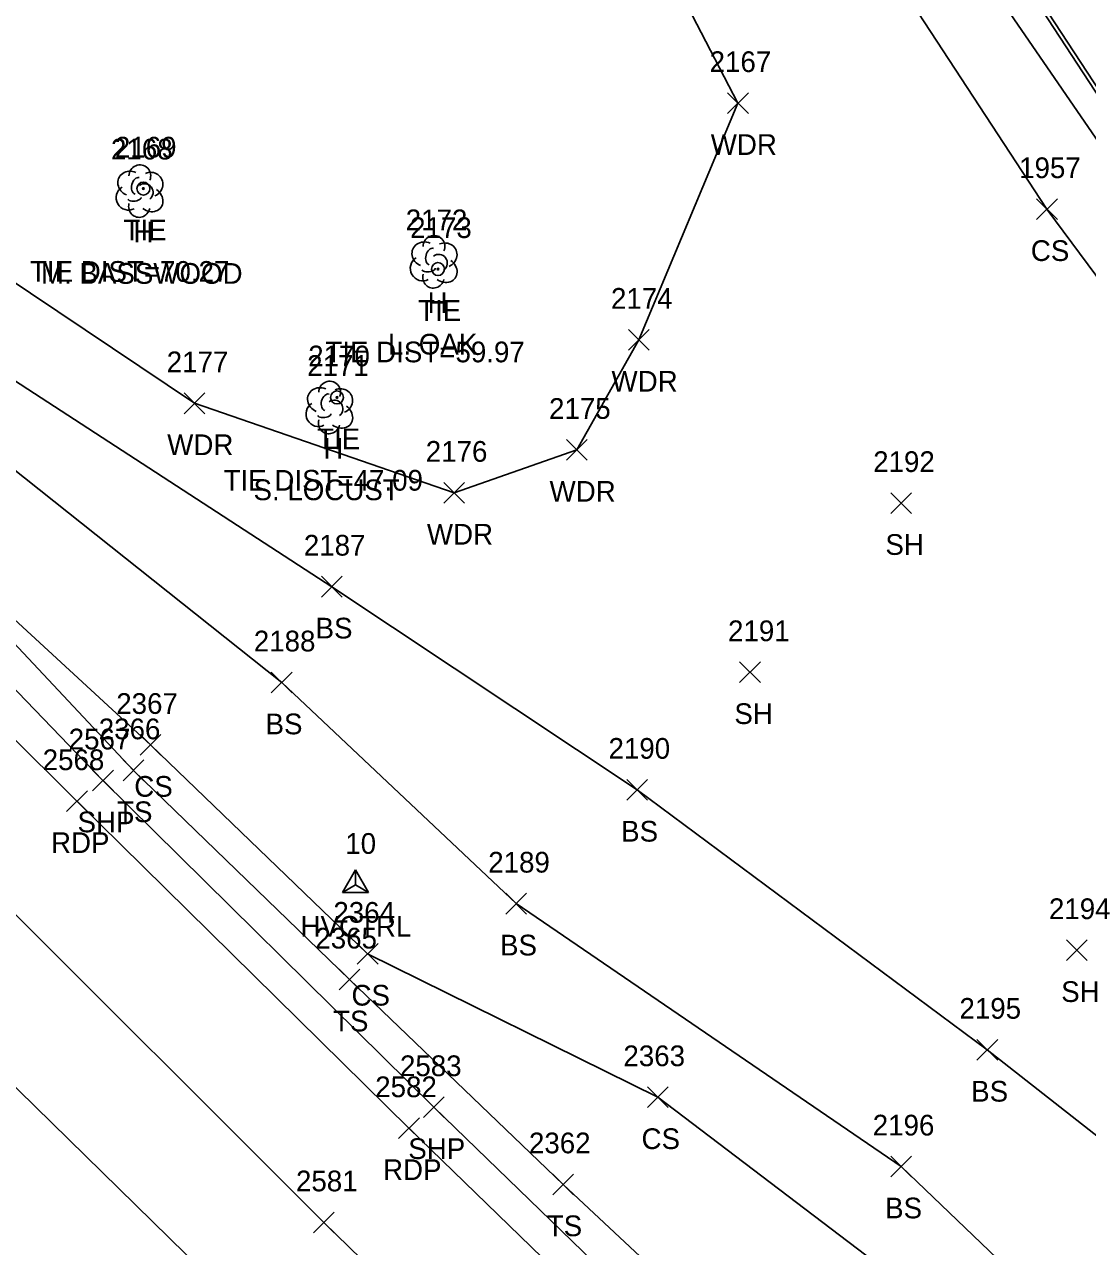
# Model space of a CAD drawing. Extents: x 1647574 to 1652703, y 212895 to 228670.
# Drawn here: x 1648054.3 to 1648157, y 227963.7 to 228081.7 of the extents above; entities that cross this region are included whole.
import ezdxf

# ---------------------------------------------------------------- set-up
doc = ezdxf.new("R2010")
doc.units = 0
for name, color, linetype in [('C_A', 7, 'Continuous'), ('C_C', 7, 'Continuous'), ('C_I', 7, 'Continuous'), ('CBP', 7, 'Continuous'), ('CPSM', 7, 'Continuous'), ('L_A', 7, 'Continuous'), ('L_C', 7, 'Continuous'), ('L_I', 7, 'Continuous'), ('L_TIC', 7, 'Continuous'), ('LAWA', 7, 'Continuous'), ('LELB', 7, 'Continuous'), ('LTD', 7, 'Continuous'), ('P_A', 7, 'Continuous'), ('P_I', 7, 'Continuous'), ('P_TIC', 7, 'Continuous'), ('PET', 7, 'Continuous'), ('PRC', 7, 'Continuous'), ('PSP', 7, 'Continuous'), ('RGR', 7, 'Continuous')]:
    doc.layers.add(name, color=color, linetype=linetype)

msp = doc.modelspace()

# ---------------------------------------------------------------- linework, layer by layer
at = {"layer": 'CBP'}
for centre, radius in [((1648065.82, 228065.87), 0.625), ((1648065.82, 228065.87), 0.0833), ((1648094.26, 228058.1), 0.625), ((1648094.26, 228058.1), 0.0833), ((1648084.51, 228045.71), 0.625), ((1648084.51, 228045.71), 0.0833)]:
    msp.add_circle(centre, radius, dxfattribs=at)
at = {"layer": 'CPSM'}
for p, q in [((1648085.05, 227997.93), (1648086.3, 228000.1)), ((1648087.55, 227997.93), (1648086.3, 228000.1)), ((1648086.3, 227998.65), (1648086.3, 228000.1)), ((1648085.05, 227997.93), (1648086.3, 227998.65)), ((1648086.3, 227998.65), (1648086.3, 227998.65)), ((1648086.3, 227998.65), (1648087.55, 227997.93)), ((1648085.05, 227997.93), (1648087.55, 227997.93))]:
    msp.add_line(p, q, dxfattribs=at)
at = {"layer": 'L_TIC'}
for points in [[(1648122.22, 228073.12), (1648124.22, 228075.12)], [(1648124.22, 228073.12), (1648122.22, 228075.12)], [(1648152.05, 228062.88), (1648154.05, 228064.88)], [(1648154.05, 228062.88), (1648152.05, 228064.88)], [(1648112.65, 228050.27), (1648114.65, 228052.27)], [(1648114.65, 228050.27), (1648112.65, 228052.27)], [(1648069.76, 228044.14), (1648071.76, 228046.14)], [(1648071.76, 228044.14), (1648069.76, 228046.14)], [(1648106.67, 228039.64), (1648108.67, 228041.64)], [(1648108.67, 228039.64), (1648106.67, 228041.64)], [(1648094.83, 228035.5), (1648096.83, 228037.5)], [(1648096.83, 228035.5), (1648094.83, 228037.5)], [(1648137.96, 228034.51), (1648139.96, 228036.51)], [(1648139.96, 228034.51), (1648137.96, 228036.51)], [(1648083, 228026.44), (1648085, 228028.44)], [(1648085, 228026.44), (1648083, 228028.44)], [(1648123.38, 228018.18), (1648125.38, 228020.18)], [(1648125.38, 228018.18), (1648123.38, 228020.18)], [(1648078.17, 228017.19), (1648080.17, 228019.19)], [(1648080.17, 228017.19), (1648078.17, 228019.19)], [(1648065.5, 228011.16), (1648067.5, 228013.16)], [(1648067.5, 228011.16), (1648065.5, 228013.16)], [(1648063.87, 228008.71), (1648065.87, 228010.71)], [(1648065.87, 228008.71), (1648063.87, 228010.71)], [(1648112.5, 228006.83), (1648114.5, 228008.83)], [(1648114.5, 228006.83), (1648112.5, 228008.83)], [(1648100.81, 227995.84), (1648102.81, 227997.84)], [(1648102.81, 227995.84), (1648100.81, 227997.84)], [(1648086.47, 227991), (1648088.47, 227993)], [(1648088.47, 227991), (1648086.47, 227993)], [(1648154.93, 227991.35), (1648156.93, 227993.35)], [(1648156.93, 227991.35), (1648154.93, 227993.35)], [(1648084.72, 227988.51), (1648086.72, 227990.51)], [(1648086.72, 227988.51), (1648084.72, 227990.51)], [(1648146.29, 227981.73), (1648148.29, 227983.73)], [(1648148.29, 227981.73), (1648146.29, 227983.73)], [(1648114.47, 227977.15), (1648116.47, 227979.15)], [(1648116.47, 227977.15), (1648114.47, 227979.15)], [(1648137.98, 227970.46), (1648139.98, 227972.46)], [(1648139.98, 227970.46), (1648137.98, 227972.46)], [(1648105.35, 227968.74), (1648107.35, 227970.74)], [(1648107.35, 227968.74), (1648105.35, 227970.74)]]:
    msp.add_lwpolyline(points, dxfattribs=at)
at = {"layer": 'LAWA'}
msp.add_lwpolyline([(1648003.3, 228303.1), (1648022.05, 228264.55), (1648045.55, 228226.26), (1648063.03, 228190.18), (1648079.22, 228154.91), (1648094.78, 228128.33), (1648111.3, 228097.1), (1648123.22, 228074.12), (1648113.65, 228051.27), (1648107.67, 228040.64), (1648095.83, 228036.5), (1648070.76, 228045.14), (1648046.97, 228061.07), (1648019.44, 228076.6), (1648008.75, 228083.44)], dxfattribs=at)
at = {"layer": 'LELB'}
for points in [[(1648351.84, 227812.3), (1648319.03, 227851.85), (1648287.09, 227892.13), (1648260.82, 227925.49), (1648232.83, 227963.62), (1648207.81, 227997.28), (1648182.57, 228032.91), (1648159.55, 228068.16), (1648135.13, 228103.7), (1648112.63, 228139.57), (1648088.44, 228176.61), (1648065.81, 228216.55), (1648048.77, 228244.34), (1648030.34, 228278.62), (1648010.32, 228316.28), (1647988.24, 228358.51), (1647969.05, 228396.12), (1647949.58, 228436.76), (1647932.55, 228474.27), (1647912.45, 228518.68), (1647893.94, 228561.09), (1647881.68, 228593.27), (1647863.51, 228642.93)], [(1648221.55, 227860.25), (1648189.85, 227891.44), (1648160.7, 227918.22), (1648135.07, 227942.85), (1648106.35, 227969.74), (1648085.72, 227989.51), (1648064.87, 228009.71), (1648037.27, 228039.1), (1648017.95, 228060.31), (1648000.53, 228079.89), (1647992.37, 228088.82), (1647945.75, 228138.02), (1647922.11, 228164.99), (1647896.22, 228195.21), (1647876.56, 228219.26), (1647857.99, 228244.57), (1647835.09, 228273.26), (1647814.45, 228301.43), (1647791.61, 228332.49), (1647765.76, 228369.8)], [(1648525.46, 227617.36), (1648497.47, 227646.51), (1648467.28, 227678.49), (1648435.31, 227710.73), (1648407.17, 227742.36), (1648379.63, 227772.76), (1648347.94, 227809.77), (1648315.69, 227849.46), (1648282.72, 227890.46), (1648255.42, 227922.98), (1648228.95, 227959.79), (1648203.39, 227994.31), (1648178.45, 228029.64), (1648153.05, 228063.88), (1648128.81, 228100.92), (1648107.87, 228136.93)], [(1648005.17, 228084.65), (1648023.65, 228068.5), (1648050.66, 228049.08), (1648084, 228027.44), (1648113.5, 228007.83), (1648147.29, 227982.73), (1648182.2, 227955.34), (1648213, 227923.38), (1648241.53, 227889), (1648267.07, 227861.14), (1648299.05, 227827.09), (1648330.77, 227794.94), (1648361.15, 227762.57), (1648392.5, 227731.8), (1648431.64, 227692.37), (1648464.56, 227657.5), (1648493.11, 227630.36), (1648521, 227603.29), (1648553.55, 227572.08), (1648564.74, 227563.33)], [(1648003.1, 228082.75), (1648021.4, 228065.95), (1648044.73, 228045.59), (1648079.17, 228018.19), (1648101.81, 227996.84), (1648138.98, 227971.46), (1648165.99, 227945.56), (1648168.81, 227943.47), (1648170.35, 227941.98), (1648172.46, 227939.54), (1648204.47, 227916.76), (1648236.47, 227884.75), (1648262.27, 227857.29), (1648293.8, 227821.06), (1648324.53, 227790.88), (1648359.53, 227760.77), (1648386.88, 227728.2), (1648427.75, 227689.04), (1648461.36, 227653.83), (1648490.92, 227628.14), (1648517.86, 227599.3), (1648549.31, 227568.74), (1648557.52, 227558.9)], [(1648258.63, 227840.47), (1648232.75, 227869.94), (1648204.84, 227901.15), (1648170.7, 227930.27), (1648148.94, 227952.73), (1648115.47, 227978.15), (1648087.47, 227992), (1648066.5, 228012.16), (1648037.27, 228039.1)]]:
    msp.add_lwpolyline(points, dxfattribs=at)
at = {"layer": 'LTD'}
for p, q in [((1648065.43, 228065.68), (1648065.43, 228065.68)), ((1648065.43, 228065.68), (1648065.43, 228065.68)), ((1648093.83, 228058.85), (1648093.83, 228058.85)), ((1648093.83, 228058.85), (1648093.83, 228058.85)), ((1648083.75, 228044.79), (1648083.75, 228044.79)), ((1648083.75, 228044.79), (1648083.75, 228044.79))]:
    msp.add_line(p, q, dxfattribs=at)
for centre in [(1648065.48, 228067.11), (1648093.87, 228060.29), (1648083.8, 228046.22)]:
    msp.add_arc(centre, 1.05, 335.5272, 180.9563, dxfattribs=at)
for centre, major_axis, ratio, start_param, end_param in [((1648064.64, 228066.35), (1.21, -0.51), 0.895232, 1.570796, 4.712389), ((1648065.22, 228066.14), (-0.208, -0.792), 0.645439, 3.141593, 6.283185), ((1648066.47, 228066.26), (-1.14, -0.48), 0.949671, 1.570796, 4.712389), ((1648064.35, 228064.97), (0.58, -1.04), 0.959034, 3.141593, 6.283185), ((1648065.93, 228065.51), (-0.5, 0.667), 0.989748, 3.141593, 6.283185), ((1648066.43, 228064.85), (-1.09, 0.79), 0.841452, 1.570796, 4.712389), ((1648064.98, 228064.93), (-0.625, -0.083), 0.423636, 0, 3.141593), ((1648065.43, 228064.18), (0.26, 1.06), 0.942809, 1.570796, 4.712389), ((1648093.04, 228059.52), (1.21, -0.51), 0.895232, 1.570796, 4.712389), ((1648093.62, 228059.31), (-0.208, -0.792), 0.645439, 3.141593, 6.283185), ((1648094.87, 228059.44), (-1.14, -0.48), 0.949671, 1.570796, 4.712389), ((1648092.74, 228058.14), (0.58, -1.04), 0.959034, 3.141593, 6.283185), ((1648094.33, 228058.69), (-0.5, 0.667), 0.989748, 3.141593, 6.283185), ((1648094.83, 228058.02), (-1.09, 0.79), 0.841452, 1.570796, 4.712389), ((1648093.83, 228057.35), (0.26, 1.06), 0.942809, 1.570796, 4.712389), ((1648093.37, 228058.1), (-0.625, -0.083), 0.423636, 0, 3.141593), ((1648082.96, 228045.45), (1.21, -0.51), 0.895232, 1.570796, 4.712389), ((1648083.54, 228045.24), (-0.208, -0.792), 0.645439, 3.141593, 6.283185), ((1648084.79, 228045.37), (-1.14, -0.48), 0.949671, 1.570796, 4.712389), ((1648082.67, 228044.08), (0.58, -1.04), 0.959034, 3.141593, 6.283185), ((1648084.25, 228044.62), (-0.5, 0.667), 0.989748, 3.141593, 6.283185), ((1648084.75, 228043.95), (-1.09, 0.79), 0.841452, 1.570796, 4.712389), ((1648083.75, 228043.29), (0.26, 1.06), 0.942809, 1.570796, 4.712389), ((1648083.29, 228044.04), (-0.625, -0.083), 0.423636, 0, 3.141593)]:
    msp.add_ellipse(centre, major_axis=major_axis, ratio=ratio, start_param=start_param, end_param=end_param, dxfattribs=at)
at = {"layer": 'P_TIC'}
for points in [[(1648060.92, 228007.73), (1648062.92, 228009.73)], [(1648062.92, 228007.73), (1648060.92, 228009.73)], [(1648058.41, 228005.73), (1648060.41, 228007.73)], [(1648060.41, 228005.73), (1648058.41, 228007.73)], [(1648092.85, 227976.19), (1648094.85, 227978.19)], [(1648094.85, 227976.19), (1648092.85, 227978.19)], [(1648090.46, 227974.16), (1648092.46, 227976.16)], [(1648092.46, 227974.16), (1648090.46, 227976.16)], [(1648082.25, 227965.07), (1648084.25, 227967.07)], [(1648084.25, 227965.07), (1648082.25, 227967.07)]]:
    msp.add_lwpolyline(points, dxfattribs=at)
at = {"layer": 'PET'}
for points in [[(1647624.94, 228569.41), (1647649.21, 228527.47), (1647673.22, 228488.91), (1647696.93, 228451.78), (1647721.59, 228414.82), (1647750.94, 228372.42), (1647776.24, 228337.3), (1647805.83, 228297.37), (1647832.4, 228262.54), (1647856.48, 228231.21), (1647884.54, 228196.61), (1647905.36, 228171.61), (1647936.05, 228137.05), (1647968.13, 228101.78), (1648000.62, 228066.78), (1648032.05, 228033.93), (1648059.41, 228006.73), (1648091.46, 227975.16), (1648125.8, 227941.82), (1648150.48, 227917.83), (1648178.42, 227890.8), (1648211.42, 227859.5)], [(1647604.45, 228556.69), (1647628.71, 228515.19), (1647652.82, 228475.82), (1647676.57, 228438.99), (1647701.85, 228401.16), (1647731.05, 228358.87), (1647757.42, 228322.24), (1647786.09, 228283.45), (1647812.17, 228249.47), (1647837.79, 228216.43), (1647865.75, 228182.07), (1647886.59, 228156.84), (1647918.79, 228120.52), (1647950.65, 228085.51), (1647982.59, 228051.21), (1648015.36, 228017.19), (1648042.42, 227989.93), (1648074.79, 227958.23), (1648108.3, 227925.38), (1648133.94, 227900.99), (1648161.33, 227874), (1648195.37, 227841.29)]]:
    msp.add_lwpolyline(points, dxfattribs=at)
at = {"layer": 'PRC'}
msp.add_lwpolyline([(1647614.42, 228562.93), (1647639.11, 228521.49), (1647662.25, 228483.93), (1647686.86, 228445.65), (1647711.57, 228408.17), (1647741.08, 228365.61), (1647766.77, 228329.38), (1647796.38, 228290.42), (1647822.34, 228255.42), (1647847.07, 228223.95), (1647875.18, 228189.36), (1647896.28, 228164.55), (1647927.3, 228129), (1647960.14, 228093.39), (1647991.4, 228058.69), (1648023.58, 228025.48), (1648050.28, 227998.95), (1648083.25, 227966.07), (1648116.97, 227933.25), (1648141.83, 227909.42), (1648169.96, 227882.31), (1648203.11, 227850.91)], dxfattribs=at)
at = {"layer": 'PSP'}
for points in [[(1648354.02, 227814.19), (1648321.06, 227853.92), (1648288.58, 227894.46), (1648263.39, 227927.38), (1648235.52, 227964.75), (1648210.1, 227999.58), (1648185.31, 228035.32), (1648161.26, 228070.47), (1648138.25, 228105.61), (1648115.28, 228141.45), (1648092.15, 228178.84), (1648068.52, 228217.79), (1648052.14, 228246.38), (1648033.46, 228279.87), (1648013.32, 228317.27), (1647991.27, 228359.8), (1647972.51, 228396.99), (1647952.45, 228438.14), (1647935.54, 228475.52), (1647915.56, 228520.25), (1647897.47, 228562.77), (1647884.83, 228594.37), (1647865.74, 228644.27)], [(1647628.26, 228570.75), (1647652.82, 228529.13), (1647676.53, 228490.5), (1647700.49, 228453.87), (1647725.49, 228416.6), (1647754.36, 228375.22), (1647780.12, 228339.14), (1647808.95, 228299.76), (1647835.07, 228264.93), (1647859.56, 228234.17), (1647887.99, 228199.58), (1647909.16, 228174.36), (1647939.11, 228140.43), (1647971.29, 228104.29), (1648003.79, 228069.19), (1648034.77, 228036.9), (1648061.92, 228008.73), (1648093.85, 227977.19), (1648128.78, 227943.39), (1648152.84, 227920.58), (1648182.1, 227892.86), (1648214.09, 227862.21)]]:
    msp.add_lwpolyline(points, dxfattribs=at)
at = {"layer": 'RGR'}
msp.add_lwpolyline([(1648353.62, 227813.75), (1648320.77, 227853.11), (1648288.36, 227894.15), (1648263.03, 227927.15), (1648235.12, 227964.21), (1648209.79, 227999.3), (1648184.57, 228034.7), (1648161.04, 228070.15), (1648137.99, 228105.47), (1648114.96, 228141.34), (1648091.9, 228178.37), (1648068.29, 228217.71), (1648051.79, 228246.29), (1648033.27, 228279.62), (1648013.01, 228317.2), (1647990.97, 228359.65), (1647972.26, 228396.89), (1647952.2, 228437.9), (1647940.84, 228461.53)], dxfattribs=at)

# ---------------------------------------------------------------- texts
at = {"layer": 'C_A'}
for s, p in [('TIE', (1648063.9, 228060.87)), ('TIE', (1648092.34, 228053.1)), ('TIE', (1648082.59, 228040.71)), ('HVCTRL', (1648080.99, 227993.65))]:
    msp.add_text(s, height=2, dxfattribs=at).set_placement(p)
at = {"layer": 'C_C'}
for s, p in [('TIE DIST=70.27', (1648054.87, 228056.87)), ('TIE DIST=59.97', (1648083.39, 228049.1)), ('TIE DIST=47.09', (1648073.56, 228036.71))]:
    msp.add_text(s, height=2, dxfattribs=at).set_placement(p)
at = {"layer": 'C_I'}
for s, p in [('2169', (1648063.07, 228068.87)), ('2173', (1648091.57, 228061.1)), ('2170', (1648081.73, 228048.71)), ('10', (1648085.31, 228001.65))]:
    msp.add_text(s, height=2, dxfattribs=at).set_placement(p)
at = {"layer": 'L_A'}
for s, p in [('WDR', (1648120.59, 228069.12)), ('H', (1648064.87, 228060.68)), ('CS', (1648151.49, 228058.88)), ('H', (1648093.26, 228053.85)), ('WDR', (1648111.01, 228046.27)), ('WDR', (1648068.12, 228040.14)), ('H', (1648083.19, 228039.79)), ('WDR', (1648105.03, 228035.64)), ('WDR', (1648093.19, 228031.5)), ('SH', (1648137.45, 228030.51)), ('BS', (1648082.44, 228022.44)), ('SH', (1648122.87, 228014.18)), ('BS', (1648077.61, 228013.19)), ('CS', (1648064.94, 228007.16)), ('TS', (1648063.28, 228004.71)), ('BS', (1648111.94, 228002.83)), ('BS', (1648100.25, 227991.84)), ('SH', (1648154.42, 227987.35)), ('CS', (1648085.91, 227987)), ('TS', (1648084.13, 227984.51)), ('BS', (1648145.73, 227977.73)), ('CS', (1648113.91, 227973.15)), ('BS', (1648137.42, 227966.46)), ('TS', (1648104.76, 227964.74))]:
    msp.add_text(s, height=2, dxfattribs=at).set_placement(p)
at = {"layer": 'L_C'}
for s, p in [('M. BASSWOOD', (1648055.93, 228056.68)), ('L. OAK', (1648089.43, 228049.85)), ('S. LOCUST', (1648076.45, 228035.79))]:
    msp.add_text(s, height=2, dxfattribs=at).set_placement(p)
at = {"layer": 'L_I'}
for s, p in [('2167', (1648120.48, 228077.12)), ('2168', (1648062.69, 228068.68)), ('1957', (1648150.36, 228066.88)), ('2172', (1648091.14, 228061.85)), ('2174', (1648110.96, 228054.27)), ('2177', (1648068.07, 228048.14)), ('2171', (1648081.63, 228047.79)), ('2175', (1648104.98, 228043.64)), ('2176', (1648093.08, 228039.5)), ('2192', (1648136.27, 228038.51)), ('2187', (1648081.31, 228030.44)), ('2191', (1648122.26, 228022.18)), ('2188', (1648076.48, 228021.19)), ('2367', (1648063.2, 228015.16)), ('2366', (1648061.51, 228012.71)), ('2190', (1648110.72, 228010.83)), ('2189', (1648099.11, 227999.84)), ('2194', (1648153.24, 227995.35)), ('2364', (1648084.16, 227995)), ('2365', (1648082.42, 227992.51)), ('2195', (1648144.6, 227985.73)), ('2363', (1648112.16, 227981.15)), ('2196', (1648136.23, 227974.46)), ('2362', (1648103.04, 227972.74))]:
    msp.add_text(s, height=2, dxfattribs=at).set_placement(p)
at = {"layer": 'P_A'}
for s, p in [('SHP', (1648059.46, 228003.73)), ('RDP', (1648056.9, 228001.73)), ('SHP', (1648091.39, 227972.19)), ('RDP', (1648088.95, 227970.16))]:
    msp.add_text(s, height=2, dxfattribs=at).set_placement(p)
at = {"layer": 'P_I'}
for s, p in [('2567', (1648058.61, 228011.73)), ('2568', (1648056.1, 228009.73)), ('2583', (1648090.59, 227980.19)), ('2582', (1648088.2, 227978.16)), ('2581', (1648080.55, 227969.07))]:
    msp.add_text(s, height=2, dxfattribs=at).set_placement(p)

doc.saveas('drawing.dxf')
